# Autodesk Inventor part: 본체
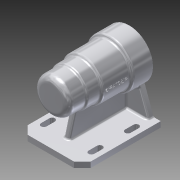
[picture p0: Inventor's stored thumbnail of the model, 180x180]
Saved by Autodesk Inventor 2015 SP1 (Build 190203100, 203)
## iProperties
Created: 2017-09
Part Number: 본체
Material: 알루미늄 6061
Document SubType Name: Modeling
Designer: C04
Density: 2.7 g/cm^3
Appearance: 알루미늄 - 평지
Mass: 695.419 g
Surface Area: 708.967 cm^2
Volume: 257.563 cm^3
Author: C04
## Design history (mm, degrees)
sketch "스케치1"
  geometry: L1 (-56, 0)-(56, 0); L2 (-56, 0)-(-56, 25); L3 (-56, 25)-(-31, 25); L4 (-31, 25)-(-31, 0); L5 (-31, 0)-(-31, 27); L6 (-31, 27)-(-11, 27); L7 (-11, 27)-(-11, 0); L8 (-11, 0)-(-11, 30); L9 (-11, 30)-(28, 30); L10 (28, 30)-(28, 0); L11 (28, 0)-(28, 34); L12 (28, 34)-(56, 34); L13 (56, 34)-(56, 0); 2 further points
  constraints: 26 end point, 7 perpendicular, 4 point on line, 3 vertical, 2 horizontal, 1 coincident, 1 midpoint
  dimensions: "d0" = 112 distance of L1.start L1.end; "d1" = 25 distance of L1.start L2.end; "d3" = 27 distance of L4.end L5.end; "d5" = 30 distance of L7.end L8.end; "d6" = 25 distance between parallel lines of L4 L2; "d7" = 45 distance between parallel lines of L7 L2; "d9" = 84 distance between parallel lines of L10 L2; "d10" = 34 distance of L10.end L11.end
revolve "회전1" sketch "스케치1" stored, may be unused: angle "d11" = 90 deg
sketch "스케치2"
  geometry: L1 (-56, -25)-(-56, 25) reference; L2 (-56, 0)-(56, 0); L3 (56, -34)-(56, 34) reference; L4 (56, 0)-(41, 0); L5 (41, 0)-(41, 21); L6 (41, 21)-(56, 21); L7 (41, 0)-(41, 24); L8 (41, 24)-(-13, 24); L9 (-13, 24)-(-13, 0); L10 (-13, 0)-(-13, 21); L11 (-13, 21)-(-25, 21); L12 (-25, 21)-(-25, 0); L13 (-25, 0)-(-25, 17.5); L14 (-25, 17.5)-(-43, 17.5); L15 (-43, 17.5)-(-43, 0); L16 (-43, 0)-(-43, 16); L17 (-43, 16)-(-47, 16); L18 (-47, 16)-(-47, 0); L19 (-47, 0)-(-47, 10.5); L20 (-47, 10.5)-(-50, 10.5); L21 (-50, 10.5)-(-50, 0); L22 (56, 21)-(56, 0); 1 further point
  constraints: 40 end point, 12 perpendicular, 12 point on line, 2 midpoint, 1 collinear
  dimensions: "d12" = 15 distance of L2.end L4.end; "d13" = 21 distance of L4.end L5.end; "d14" = 24 distance of L4.end L7.end; "d15" = 54 distance of L7.end L8.end; "d16" = 21 distance of L9.end L10.end; "d17" = 12 distance of L10.end L11.end; "d18" = 17.5 distance of L12.end L13.end; "d19" = 18 distance of L13.end L14.end; "d20" = 16 distance of L15.end L16.end; "d21" = 4 distance of L16.end L17.end; "d22" = 10.5 distance of L18.end L19.end; "d23" = 3 distance of L19.end L20.end
revolve "회전2" sketch "스케치2" stored, may be unused: angle "d25" = 90 deg
sketch "스케치3" dims "d26" = 52
  geometry: 3 further points
  constraints: 2 vertical alignment, 1 coincident, 2 other
hole "구멍1" sketch "스케치3" at (0, 26) diameter "d27" = 3.242; stored, may be unused: countersink angle "d31" = 90 deg, drill point angle "d33" = 118 deg; dims "d28" = 8, "d29" = 4, "d30" = 2, "d32" = 11
node "작업 평면1"
sketch "스케치4"
  geometry: L1 (-56, 45)-(56, 45); L2 (56, 45)-(56, -45); L3 (56, -45)-(-56, -45); L4 (-56, -45)-(-56, 45); L5 (56, -34)-(56, 34) reference; L6 (-56, 0)-(56, 0); L7 (-56, 34)-(56, 34); L8 (-56, -34)-(56, -34); L9 (32, 45)-(32, -45); L10 (20, 45)-(20, -45); L11 (-20, 45)-(-20, -45); L12 (-32, 45)-(-32, -45); L13 (-32, -34)-(-20, -34); L14 (-32, -38)-(-20, -38); L15 (-20, -30)-(-32, -30); L16 (20, -34)-(32, -34); L17 (20, -38)-(32, -38); L18 (32, -30)-(20, -30); L19 (20, 34)-(32, 34); L20 (28, 34)-(56, 34) reference; L21 (20, 30)-(32, 30); L22 (32, 38)-(20, 38); L23 (-32, 34)-(-20, 34); L24 (-32, 30)-(-20, 30); L25 (-20, 38)-(-32, 38); A1 r 4 centre (-32, -34) between (-32, -30) and (-32, -38); A2 r 4 centre (-20, -34) between (-20, -38) and (-20, -30); A3 r 4 centre (20, -34) between (20, -30) and (20, -38); A4 r 4 centre (32, -34) between (32, -38) and (32, -30); A5 r 4 centre (20, 34) between (20, 38) and (20, 30); A6 r 4 centre (32, 34) between (32, 30) and (32, 38); A7 r 4 centre (-32, 34) between (-32, 38) and (-32, 30); A8 r 4 centre (-20, 34) between (-20, 30) and (-20, 38); 8 further points
  constraints: 54 end point, 24 point on line, 16 point on circle, 16 tangent, 10 midpoint, 9 parallel, 8 centre point, 5 perpendicular, 2 vertical alignment, 1 horizontal, 1 vertical
  dimensions: "d38" = 90 distance of L1.end L2.end; "d39" = 112 distance of L1.start L1.end; "d42" = 34 distance of L6.start L7.start; "d43" = 34 distance of L8.start L6.start; "d44" = 11 distance between parallel lines of L1 L7; "d45" = 24 distance of L2.end L9.end; "d46" = 12 distance of L10.end L9.end; "d47" = 40 distance of L10.end L11.end; "d48" = 12 distance of L11.end L12.end; "d49" = 4 radius of A2; "d50" = 4 radius of A4; "d51" = 4 radius of A6; "d52" = 4 radius of A8
extrude "돌출1" join sketch "스케치4" distance "d53" = 8; taper "d54" = 0 deg
sketch "스케치5"
  geometry: L1 (0, 8)-(90, 8) reference; L2 (10, 8)-(24.57, 48.031); L3 (80, 8)-(65.43, 48.031); L4 (10, 8)-(80, 8); A1 r 30 centre (45, 70) between (24.57, 48.031) and (65.43, 48.031) reference; A2 r 30 centre (45, 70) between (24.57, 48.031) and (65.43, 48.031); 1 further point
  constraints: 6 end point, 4 point on circle, 2 point on line, 1 centre point, 1 coincident, 1 collinear
  dimensions: "d55" = 110 deg angle of L1 L2; "d56" = 110 deg angle of L1 L3; "d57" = 10 distance of L2.start L1.start; "d58" = 10 distance of L3.start L1.end
extrude "돌출2" join sketch "스케치5" distance "d59" = 8; taper "d60" = 0 deg
sketch "스케치6"
  geometry: L1 (56, -62)-(-56, -62) reference; L2 (-34, -62)-(-23.87, -24.193); L3 (56, -70)-(-56, -70) reference; L4 (-23.87, -24.193)-(-6.135, -26.657); L5 (-6.135, -26.657)-(32.198, -27.923); L6 (32.198, -27.923)-(50.642, -31.72); L7 (50.642, -31.72)-(50.642, -62); L8 (-34, -62)-(50.642, -62); 1 further point
  constraints: 12 end point, 2 point on line, 1 collinear, 1 perpendicular
  dimensions: "d62" = 22 horizontal distance of L2.start L3.end; "d63" = 105 deg angle of L1 L2; "d64" = 30.28018 distance of L6.end L7.end; "d65" = 18.44351 horizontal distance of L5.end L6.end; "d66" = 38.33356 horizontal distance of L4.end L5.end; "d67" = 17.73437 horizontal distance of L2.end L4.end; "d68" = 97.089 deg angle of L2 L4; "d69" = 170.258 deg angle of L6 L5; "d70" = 101.634 deg angle of L7 L6
extrude "돌출3" join sketch "스케치6" stored distance "d71" = 8; taper "d72" = 0 deg
chamfer "모따기1" distance "d73" = 12; stored, may be unused: second distance "d74" = 2, angle "d75" = 45 deg
fillet "모깎기1" dims "d76" = 9
fillet "모깎기2" dims "d77" = 3
fillet "모깎기3" dims "d78" = 3
chamfer "모따기2" distance "d79" = 1; stored, may be unused: second distance "d80" = 2, angle "d81" = 45 deg
fillet "모깎기4" dims "d82" = 0.3
node "작업 평면2"
sketch "스케치7"
  geometry: L1 (47.5, -26.008)-(47.5, 34) reference; 2 further points
  constraints: 1 horizontal alignment, 1 other
  dimensions: "d83" = 48 distance from line of L1 point (-0.5, 0)
feature "엠보싱1" sketch "스케치7" dims "d0" = 112, "d1" = 25, "d3" = 27, "d5" = 30, "d6" = 25, "d7" = 45, "d9" = 84, "d10" = 34, "d84" = 0.5, "d85" = 0
node "솔리드1"
pattern_circular "원형 패턴1" dims angle "d35" = 360 deg
